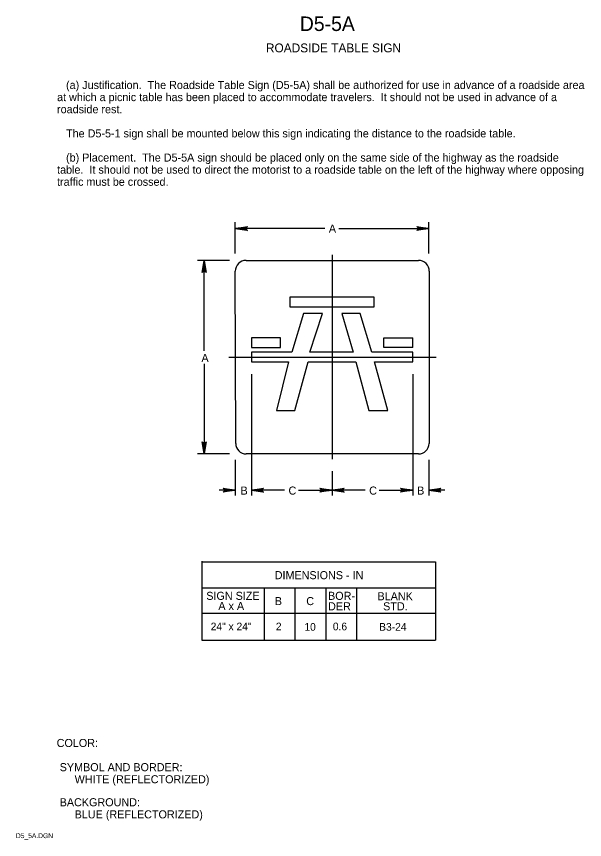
# Model space of a CAD drawing. Extents: x 0.013 to 0.189, y 0.004 to 0.259.
import ezdxf

# ---------------------------------------------------------------- set-up
doc = ezdxf.new("R2010")
doc.units = 0
for name, color, linetype in [('1', 7, 'Continuous'), ('2', 7, 'Continuous'), ('3', 7, 'Continuous')]:
    doc.layers.add(name, color=color, linetype=linetype)

# ---------------------------------------------------------------- blocks, each defined once
blk = doc.blocks.new('RARROW')
at = {"layer": '3'}
for p, q in [((-2.156, 0.285), (-2.2665, 0.384625)), ((-2.2665, 0.384625), (0, 0)), ((0, 0), (-2.2665, -0.379125)), ((-2.156, 0.285), (-2.075625, 0.12075)), ((0, 0), (-2.156, 0.285)), ((-2.14975, -0.2705), (0, 0)), ((-2.075625, 0.12075), (0, 0)), ((0, 0), (-2.074, -0.108)), ((-2.2665, -0.379125), (-2.14975, -0.2705)), ((-2.074, -0.108), (-2.14975, -0.2705))]:
    blk.add_line(p, q, dxfattribs=at)

msp = doc.modelspace()

# ---------------------------------------------------------------- linework, layer by layer
at = {"layer": '3'}
for p, q in [((0.0805, 0.18567), (0.0805, 0.19537)), ((0.1405, 0.18567), (0.1405, 0.19537)), ((0.10825, 0.19337), (0.0805, 0.19337)), ((0.11263, 0.19337), (0.1405, 0.19337)), ((0.1105, 0.18525), (0.1105, 0.12187)), ((0.07871, 0.1835), (0.06875, 0.1835)), ((0.07088, 0.1555), (0.07088, 0.1835)), ((0.08387, 0.1835), (0.13725, 0.1835)), ((0.08063, 0.12675), (0.0805, 0.18012)), ((0.14062, 0.18012), (0.14062, 0.12675)), ((0.1235, 0.17213), (0.09738, 0.17213)), ((0.09738, 0.17213), (0.09738, 0.16912)), ((0.1235, 0.16912), (0.1235, 0.17213)), ((0.09738, 0.16912), (0.1235, 0.16912)), ((0.10163, 0.167), (0.098, 0.155)), ((0.1075, 0.167), (0.10163, 0.167)), ((0.10363, 0.155), (0.1075, 0.167)), ((0.11925, 0.167), (0.1135, 0.167)), ((0.1135, 0.167), (0.117, 0.155)), ((0.12287, 0.155), (0.11925, 0.167)), ((0.0945, 0.1595), (0.0855, 0.1595)), ((0.0855, 0.1595), (0.0855, 0.1565)), ((0.0945, 0.1565), (0.0945, 0.1595)), ((0.1265, 0.1565), (0.1265, 0.1595)), ((0.1265, 0.1595), (0.1355, 0.1595)), ((0.1355, 0.1565), (0.1355, 0.1595)), ((0.0855, 0.1565), (0.0945, 0.1565)), ((0.1355, 0.1565), (0.1265, 0.1565)), ((0.0785, 0.1535), (0.14275, 0.1535)), ((0.098, 0.155), (0.0855, 0.155)), ((0.0855, 0.155), (0.0855, 0.152)), ((0.0855, 0.1535), (0.09738, 0.1535)), ((0.1035, 0.1535), (0.11738, 0.1535)), ((0.117, 0.155), (0.10363, 0.155)), ((0.1355, 0.155), (0.12287, 0.155)), ((0.1355, 0.152), (0.1355, 0.155)), ((0.07088, 0.15138), (0.07088, 0.1235)), ((0.0855, 0.152), (0.097, 0.152)), ((0.097, 0.152), (0.09325, 0.137)), ((0.099, 0.137), (0.10313, 0.152)), ((0.10313, 0.152), (0.11788, 0.152)), ((0.11788, 0.152), (0.12187, 0.137)), ((0.12775, 0.137), (0.12362, 0.152)), ((0.12362, 0.152), (0.1355, 0.152)), ((0.0855, 0.14825), (0.0855, 0.11063)), ((0.1355, 0.14825), (0.1355, 0.11063)), ((0.09325, 0.137), (0.099, 0.137)), ((0.12187, 0.137), (0.12775, 0.137)), ((0.07871, 0.1235), (0.06875, 0.1235)), ((0.13725, 0.1235), (0.08387, 0.1235)), ((0.0805, 0.12162), (0.0805, 0.11063)), ((0.1405, 0.12162), (0.1405, 0.11063)), ((0.1105, 0.11813), (0.1105, 0.11063)), ((0.0805, 0.11225), (0.0755, 0.11225)), ((0.09575, 0.11225), (0.0855, 0.11225)), ((0.10013, 0.11225), (0.1105, 0.11225)), ((0.12075, 0.11225), (0.1105, 0.11225)), ((0.12513, 0.11225), (0.1355, 0.11225)), ((0.1455, 0.11225), (0.1405, 0.11225)), ((0.07014, 0.09029), (0.07014, 0.06579)), ((0.07014, 0.09004), (0.14258, 0.09004)), ((0.14252, 0.09008), (0.14252, 0.06579)), ((0.14258, 0.08192), (0.07014, 0.08192)), ((0.08942, 0.08201), (0.08942, 0.06579)), ((0.09891, 0.08201), (0.09891, 0.06579)), ((0.10854, 0.08176), (0.10854, 0.06579)), ((0.11803, 0.08176), (0.11803, 0.06579)), ((0.07014, 0.07417), (0.14258, 0.07417)), ((0.07014, 0.06579), (0.14258, 0.06579))]:
    msp.add_line(p, q, dxfattribs=at)
for centre, radius, start, end in [((0.08387, 0.18012), 0.00337, 90, 180), ((0.13725, 0.18012), 0.00338, 0, 90), ((0.08387, 0.12675), 0.00325, 180, 270), ((0.13731, 0.12681), 0.00331, 268.9191, 358.9191)]:
    msp.add_arc(centre, radius, start, end, dxfattribs=at)

# ---------------------------------------------------------------- block references
at = {"layer": '3', "xscale": 0.0016545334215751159, "yscale": 0.0016366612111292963}
for p, rotation in [((0.0805, 0.19337), 180), ((0.07088, 0.1835), 90), ((0.07088, 0.1235), -90), ((0.0855, 0.11225), 180), ((0.1105, 0.11225), 180), ((0.1405, 0.11225), 180)]:
    msp.add_blockref('RARROW', p, dxfattribs=dict(at, rotation=rotation))
for p in [(0.1405, 0.19337), (0.0805, 0.11225), (0.1105, 0.11225), (0.1355, 0.11225)]:
    msp.add_blockref('RARROW', p, dxfattribs=at)

# ---------------------------------------------------------------- texts
at = {"layer": '1'}
for s, height, p in [('D5-5A', 0.0045, (0.1005, 0.25462)), ('ROADSIDE TABLE SIGN', 0.0027503, (0.09, 0.248)), ('COLOR:', 0.0025, (0.02513, 0.03263)), (' SYMBOL AND BORDER:', 0.0024998, (0.02513, 0.02513)), ('      WHITE (REFLECTORIZED)', 0.0024998, (0.02513, 0.02138)), (' BACKGROUND:', 0.0024998, (0.02513, 0.01425)), ('      BLUE (REFLECTORIZED)', 0.0024998, (0.02513, 0.0105))]:
    msp.add_text(s, height=height, dxfattribs=at).set_placement(p)
at = {"layer": '2'}
for s, height, p in [('   (a) Justification.  The Roadside Table Sign (D5-5A) shall be authorized for use in advance of a roadside area', 0.00249975, (0.02525, 0.23663)), ('at which a picnic table has been placed to accommodate travelers.  It should not be used in advance of a', 0.00249975, (0.02525, 0.23287)), ('roadside rest.', 0.0024998, (0.02525, 0.22912)), ('   The D5-5-1 sign shall be mounted below this sign indicating the distance to the roadside table.', 0.0024998, (0.02525, 0.22163)), ('   (b) Placement.  The D5-5A sign should be placed only on the same side of the highway as the roadside', 0.00249975, (0.02525, 0.21413)), ('table.  It should not be used to direct the motorist to a roadside table on the left of the highway where opposing', 0.00249975, (0.02525, 0.21038)), ('traffic must be crossed.', 0.0024998, (0.02525, 0.20663))]:
    msp.add_text(s, height=height, dxfattribs=at).set_placement(p)
at = {"layer": '3'}
for s, height, p in [('A', 0.0025, (0.1095, 0.19212)), ('A', 0.0025, (0.07, 0.152)), ('B', 0.0025, (0.08213, 0.11088)), ('C', 0.0025, (0.097, 0.11088)), ('C', 0.0025, (0.122, 0.11088)), ('B', 0.0025, (0.13687, 0.11088)), ('DIMENSIONS - IN', 0.0024998, (0.09272, 0.08466)), ('SIGN SIZE', 0.0025, (0.0715, 0.07825)), ('B', 0.0025, (0.09275, 0.07662)), ('C', 0.0025, (0.1025, 0.07662)), ('BOR-', 0.0025, (0.10925, 0.07825)), ('BLANK', 0.0025, (0.12458, 0.07812)), ('A x A', 0.0025, (0.07525, 0.07512)), ('DER', 0.0025, (0.10925, 0.075)), ('STD.', 0.0025, (0.12633, 0.075)), ('24" x 24"', 0.002375, (0.07287, 0.06881)), ('2', 0.00238, (0.09307, 0.06881)), ('10', 0.002375, (0.10192, 0.06869)), ('0.6', 0.002375, (0.11074, 0.06881)), ('B3-24', 0.002375, (0.12511, 0.06869)), ('D5_5A.DGN', 0.0015, (0.0125, 0.00438))]:
    msp.add_text(s, height=height, dxfattribs=at).set_placement(p)

doc.saveas('drawing.dxf')
